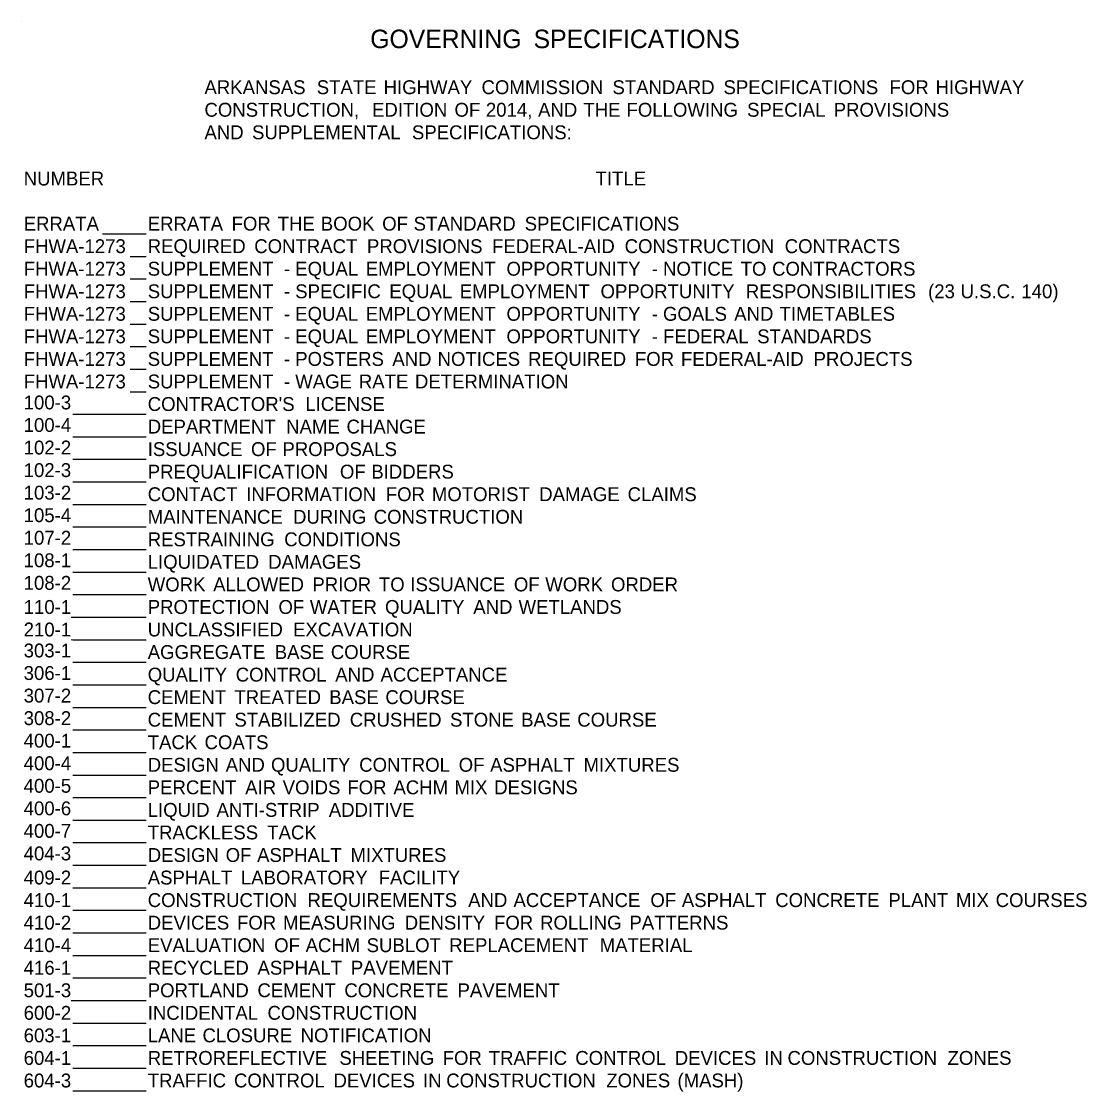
# Model space of a CAD drawing. Extents: x 2713 to 4149, y 471 to 1457.
# Drawn here: x 2713.2 to 3173.7, y 982.5 to 1445.3 of the extents above; entities that cross this region are included whole.
import ezdxf

# ---------------------------------------------------------------- set-up
doc = ezdxf.new("R2010")
doc.units = 0
doc.layers.add('Default', color=7, linetype='Continuous')
doc.layers.add('R_Border', color=7, linetype='Continuous')

msp = doc.modelspace()

# ---------------------------------------------------------------- linework, layer by layer
at = {"layer": 'R_Border'}
for p, q in [((2713.24, 1445.27), (2713.24, 1445.27)), ((2748.33, 1353.41), (2767.2, 1353.41)), ((2760.31, 1343.66), (2767.2, 1343.66)), ((2760.31, 1333.91), (2767.2, 1333.91)), ((2760.31, 1324.16), (2767.2, 1324.16)), ((2760.31, 1314.41), (2767.2, 1314.41)), ((2760.31, 1304.66), (2767.2, 1304.66)), ((2760.31, 1294.91), (2767.2, 1294.91)), ((2760.31, 1285.16), (2767.2, 1285.16)), ((2735.51, 1275.41), (2767.2, 1275.41)), ((2735.51, 1265.66), (2767.2, 1265.66)), ((2735.51, 1255.91), (2767.2, 1255.91)), ((2735.51, 1246.16), (2767.2, 1246.16)), ((2735.51, 1236.41), (2767.2, 1236.41)), ((2735.51, 1226.66), (2767.2, 1226.66)), ((2735.51, 1216.91), (2767.2, 1216.91)), ((2735.51, 1207.16), (2767.2, 1207.16)), ((2735.51, 1197.41), (2767.2, 1197.41)), ((2735.51, 1187.66), (2767.2, 1187.66)), ((2735.51, 1177.91), (2767.2, 1177.91)), ((2735.51, 1168.16), (2767.2, 1168.16)), ((2735.51, 1158.41), (2767.2, 1158.41)), ((2735.51, 1148.66), (2767.2, 1148.66)), ((2735.51, 1138.91), (2767.2, 1138.91)), ((2735.51, 1129.16), (2767.2, 1129.16)), ((2735.51, 1119.41), (2767.2, 1119.41)), ((2735.51, 1109.66), (2767.2, 1109.66)), ((2735.51, 1099.91), (2767.2, 1099.91)), ((2735.51, 1090.16), (2767.2, 1090.16)), ((2735.51, 1080.41), (2767.2, 1080.41)), ((2735.51, 1070.66), (2767.2, 1070.66)), ((2735.51, 1060.91), (2767.2, 1060.91)), ((2735.51, 1051.16), (2767.2, 1051.16)), ((2735.51, 1041.41), (2767.2, 1041.41)), ((2735.51, 1031.66), (2767.2, 1031.66)), ((2735.51, 1021.91), (2767.2, 1021.91)), ((2735.51, 1012.16), (2767.2, 1012.16)), ((2735.51, 1002.41), (2767.2, 1002.41)), ((2735.51, 992.66), (2767.2, 992.66)), ((2735.51, 982.91), (2767.2, 982.91))]:
    msp.add_line(p, q, dxfattribs=at)

# ---------------------------------------------------------------- texts
at = {"layer": 'Default'}
for s, height, p in [('GOVERNING', 8, (2864.03, 1433.71)), (' SPECIFICATIONS', 8, (2931.67, 1433.71)), ('           ARKANSAS', 6, (2767.84, 1413.81)), (' STATE', 6, (2838.67, 1413.81)), (' HIGHWAY', 6, (2867.58, 1413.81)), (' COMMISSION', 6, (2909.9, 1413.81)), (' STANDARD', 6, (2966.5, 1413.81)), (' SPECIFICATIONS', 6, (3014.5, 1413.81)), (' FOR', 6, (3086.27, 1413.81)), (' HIGHWAY', 6, (3106.18, 1413.81)), ('           CONSTRUCTION,', 6, (2767.84, 1404.06)), (' EDITION', 6, (2862.56, 1404.06)), (' OF', 6, (2898.21, 1404.06)), (' 2014,', 6, (2911.79, 1404.06)), (' AND', 6, (2934.34, 1404.06)), (' THE', 6, (2953.93, 1404.06)), (' FOLLOWING', 6, (2972.58, 1404.06)), (' SPECIAL', 6, (3024.68, 1404.06)), (' PROVISIONS', 6, (3062.12, 1404.06)), ('           AND', 6, (2767.84, 1394.31)), (' SUPPLEMENTAL', 6, (2810.7, 1394.31)), (' SPECIFICATIONS:', 6, (2879.82, 1394.31)), ('NUMBER', 6, (2714.22, 1374.32)), ('TITLE', 6, (2961.4, 1374.32)), ('ERRATA', 6, (2714.22, 1354.82)), ('ERRATA', 6, (2767.84, 1354.82)), (' FOR', 6, (2801.86, 1354.82)), (' THE', 6, (2821.78, 1354.82)), (' BOOK', 6, (2840.43, 1354.82)), (' OF', 6, (2866.96, 1354.82)), (' STANDARD', 6, (2880.55, 1354.82)), (' SPECIFICATIONS', 6, (2928.55, 1354.82)), ('FHWA-1273', 6, (2714.22, 1345.07)), ('REQUIRED', 6, (2767.84, 1345.07)), (' CONTRACT', 6, (2811.65, 1345.07)), (' PROVISIONS', 6, (2860.38, 1345.07)), (' FEDERAL-AID', 6, (2914.45, 1345.07)), (' CONSTRUCTION', 6, (2971.77, 1345.07)), (' CONTRACTS', 6, (3040.95, 1345.07)), ('FHWA-1273', 6, (2714.22, 1335.32)), ('SUPPLEMENT', 6, (2767.84, 1335.32)), (' -', 6, (2824.51, 1335.32)), (' EQUAL', 6, (2829.37, 1335.32)), (' EMPLOYMENT', 6, (2859.82, 1335.32)), (' OPPORTUNITY', 6, (2920.68, 1335.32)), (' -', 6, (2983.5, 1335.32)), (' NOTICE', 6, (2988.35, 1335.32)), (' TO', 6, (3021.91, 1335.32)), (' CONTRACTORS', 6, (3035.5, 1335.32)), ('FHWA-1273', 6, (2714.22, 1325.57)), ('SUPPLEMENT', 6, (2767.84, 1325.57)), (' -', 6, (2824.51, 1325.57)), (' SPECIFIC', 6, (2829.37, 1325.57)), (' EQUAL', 6, (2870.03, 1325.57)), (' EMPLOYMENT', 6, (2900.48, 1325.57)), (' OPPORTUNITY', 6, (2961.34, 1325.57)), (' RESPONSIBILITIES', 6, (3024.16, 1325.57)), (' (23', 6, (3102.92, 1325.57)), (' U.S.C.', 6, (3116.98, 1325.57)), (' 140)', 6, (3143.26, 1325.57)), ('FHWA-1273', 6, (2714.22, 1315.82)), ('SUPPLEMENT', 6, (2767.84, 1315.82)), (' EQUAL', 6, (2829.37, 1315.82)), (' EMPLOYMENT', 6, (2859.82, 1315.82)), (' OPPORTUNITY', 6, (2920.68, 1315.82)), (' GOALS', 6, (2988.35, 1315.82)), (' AND', 6, (3019.13, 1315.82)), (' TIMETABLES', 6, (3038.71, 1315.82)), (' -', 6, (2824.51, 1315.82)), (' -', 6, (2983.5, 1315.82)), ('FHWA-1273', 6, (2714.22, 1306.07)), ('SUPPLEMENT', 6, (2767.84, 1306.07)), (' EQUAL', 6, (2829.37, 1306.07)), (' EMPLOYMENT', 6, (2859.82, 1306.07)), (' OPPORTUNITY', 6, (2920.68, 1306.07)), (' FEDERAL', 6, (2988.35, 1306.07)), (' STANDARDS', 6, (3029.06, 1306.07)), (' -', 6, (2824.51, 1306.07)), (' -', 6, (2983.5, 1306.07)), ('FHWA-1273', 6, (2714.22, 1296.32)), ('SUPPLEMENT', 6, (2767.84, 1296.32)), (' POSTERS', 6, (2829.37, 1296.32)), (' AND', 6, (2871.33, 1296.32)), (' NOTICES', 6, (2890.91, 1296.32)), (' REQUIRED', 6, (2930.06, 1296.32)), (' FOR', 6, (2976.2, 1296.32)), (' FEDERAL-AID', 6, (2996.11, 1296.32)), (' PROJECTS', 6, (3053.43, 1296.32)), (' -', 6, (2824.51, 1296.32)), ('FHWA-1273', 6, (2714.22, 1286.57)), ('SUPPLEMENT', 6, (2767.84, 1286.57)), (' WAGE', 6, (2829.37, 1286.57)), (' RATE', 6, (2856.87, 1286.57)), (' DETERMINATION', 6, (2881.11, 1286.57)), (' -', 6, (2824.51, 1286.57)), ('100-3', 6, (2714.22, 1277.5)), ("CONTRACTOR'S", 6, (2767.84, 1276.82)), (' LICENSE', 6, (2833.75, 1276.82)), ('100-4', 6, (2714.22, 1267.75)), ('DEPARTMENT', 6, (2767.84, 1267.07)), (' NAME', 6, (2825.43, 1267.07)), (' CHANGE', 6, (2851.54, 1267.07)), ('102-2', 6, (2714.22, 1258)), ('ISSUANCE', 6, (2767.84, 1257.32)), (' OF', 6, (2810.26, 1257.32)), (' PROPOSALS', 6, (2823.84, 1257.32)), ('102-3', 6, (2714.22, 1248.25)), ('PREQUALIFICATION', 6, (2767.84, 1247.57)), (' OF', 6, (2848.68, 1247.57)), (' BIDDERS', 6, (2862.26, 1247.57)), ('103-2', 6, (2714.22, 1238.5)), ('CONTACT', 6, (2767.84, 1237.82)), (' INFORMATION', 6, (2808.19, 1237.82)), (' FOR', 6, (2868.52, 1237.82)), (' MOTORIST', 6, (2888.43, 1237.82)), (' DAMAGE', 6, (2934.83, 1237.82)), (' CLAIMS', 6, (2973.05, 1237.82)), ('105-4', 6, (2714.22, 1228.75)), ('MAINTENANCE', 6, (2767.84, 1228.07)), (' DURING', 6, (2828.42, 1228.07)), (' CONSTRUCTION', 6, (2863.29, 1228.07)), ('107-2', 6, (2714.22, 1219)), ('RESTRAINING', 6, (2767.84, 1218.32)), (' CONDITIONS', 6, (2824.61, 1218.32)), ('108-1', 6, (2714.22, 1209.25)), ('LIQUIDATED', 6, (2767.84, 1208.57)), (' DAMAGES', 6, (2817.7, 1208.57)), ('108-2', 6, (2714.22, 1199.5)), ('WORK', 6, (2767.84, 1198.82)), (' ALLOWED', 6, (2793.9, 1198.82)), (' PRIOR', 6, (2836.78, 1198.82)), (' TO', 6, (2865.54, 1198.82)), (' ISSUANCE', 6, (2879.14, 1198.82)), (' OF', 6, (2923.88, 1198.82)), (' WORK', 6, (2937.47, 1198.82)), (' ORDER', 6, (2965.86, 1198.82)), ('110-1______', 6, (2714.22, 1189.07)), ('PROTECTION', 6, (2767.84, 1189.07)), (' OF', 6, (2822.12, 1189.07)), (' WATER', 6, (2835.71, 1189.07)), (' QUALITY', 6, (2868.19, 1189.07)), (' AND', 6, (2906.33, 1189.07)), (' WETLANDS', 6, (2925.91, 1189.07)), ('210-1______', 6, (2714.22, 1179.32)), ('UNCLASSIFIED', 6, (2767.84, 1179.32)), (' EXCAVATION', 6, (2828.42, 1179.32)), ('303-1', 6, (2714.22, 1170.25)), ('AGGREGATE', 6, (2767.84, 1169.57)), (' BASE', 6, (2820.51, 1169.57)), (' COURSE', 6, (2844.76, 1169.57)), ('306-1', 6, (2714.22, 1160.5)), ('QUALITY', 6, (2767.84, 1159.82)), (' CONTROL', 6, (2803.65, 1159.82)), (' AND', 6, (2846.67, 1159.82)), (' ACCEPTANCE', 6, (2866.25, 1159.82)), ('307-2', 6, (2714.22, 1150.75)), ('CEMENT', 6, (2767.84, 1150.07)), (' TREATED', 6, (2803.07, 1150.07)), (' BASE', 6, (2844.08, 1150.07)), (' COURSE', 6, (2868.34, 1150.07)), ('308-2', 6, (2714.22, 1141)), ('CEMENT', 6, (2767.84, 1140.32)), (' STABILIZED', 6, (2803.07, 1140.32)), (' CRUSHED', 6, (2852.94, 1140.32)), (' STONE', 6, (2896.28, 1140.32)), (' BASE', 6, (2927.04, 1140.32)), (' COURSE', 6, (2951.29, 1140.32)), ('400-1', 6, (2714.22, 1131.25)), ('TACK', 6, (2767.84, 1130.57)), (' COATS', 6, (2790.18, 1130.57)), ('400-4', 6, (2714.22, 1121.5)), ('DESIGN', 6, (2767.84, 1120.82)), (' AND', 6, (2799.3, 1120.82)), (' QUALITY', 6, (2818.88, 1120.82)), (' CONTROL', 6, (2857.02, 1120.82)), (' OF', 6, (2900.04, 1120.82)), (' ASPHALT', 6, (2913.62, 1120.82)), (' MIXTURES', 6, (2953.99, 1120.82)), ('400-5', 6, (2714.22, 1111.75)), ('PERCENT', 6, (2767.84, 1111.07)), (' AIR', 6, (2807.74, 1111.07)), (' VOIDS', 6, (2823.93, 1111.07)), (' FOR', 6, (2851.9, 1111.07)), (' ACHM', 6, (2871.82, 1111.07)), (' MIX', 6, (2898.2, 1111.07)), (' DESIGNS', 6, (2915.38, 1111.07)), ('400-6', 6, (2714.22, 1102)), ('LIQUID', 6, (2767.84, 1101.32)), (' ANTI-STRIP', 6, (2795.34, 1101.32)), (' ADDITIVE', 6, (2843.88, 1101.32)), ('400-7', 6, (2714.22, 1092.25)), ('TRACKLESS', 6, (2767.84, 1091.57)), (' TACK', 6, (2817.26, 1091.57)), ('404-3', 6, (2714.22, 1082.5)), ('DESIGN', 6, (2767.84, 1081.82)), (' OF', 6, (2799.3, 1081.82)), (' ASPHALT', 6, (2812.89, 1081.82)), (' MIXTURES', 6, (2853.25, 1081.82)), ('409-2', 6, (2714.22, 1072.07)), ('ASPHALT', 6, (2767.84, 1072.07)), (' LABORATORY', 6, (2805.88, 1072.07)), (' FACILITY', 6, (2865.45, 1072.07)), ('410-1', 6, (2714.22, 1062.32)), ('CONSTRUCTION', 6, (2767.84, 1062.32)), (' REQUIREMENTS', 6, (2834.69, 1062.32)), (' AND', 6, (2904.13, 1062.32)), (' ACCEPTANCE', 6, (2923.71, 1062.32)), (' OF', 6, (2982.89, 1062.32)), (' ASPHALT', 6, (2996.48, 1062.32)), (' CONCRETE', 6, (3036.85, 1062.32)), (' PLANT', 6, (3085.78, 1062.32)), (' MIX', 6, (3114.96, 1062.32)), (' COURSES', 6, (3132.13, 1062.32)), ('410-2', 6, (2714.22, 1052.57)), ('DEVICES', 6, (2767.84, 1052.57)), (' FOR', 6, (2804.21, 1052.57)), (' MEASURING', 6, (2824.12, 1052.57)), (' DENSITY', 6, (2876.7, 1052.57)), (' FOR', 6, (2915.3, 1052.57)), (' ROLLING', 6, (2935.21, 1052.57)), (' PATTERNS', 6, (2973.82, 1052.57)), ('410-4', 6, (2714.22, 1042.82)), ('EVALUATION', 6, (2767.84, 1042.82)), (' OF', 6, (2820.27, 1042.82)), (' ACHM', 6, (2833.85, 1042.82)), (' SUBLOT', 6, (2860.24, 1042.82)), (' REPLACEMENT', 6, (2895.94, 1042.82)), (' MATERIAL', 6, (2960.99, 1042.82)), ('416-1', 6, (2714.22, 1033.07)), ('RECYCLED', 6, (2767.84, 1033.07)), (' ASPHALT', 6, (2813.05, 1033.07)), (' PAVEMENT', 6, (2853.42, 1033.07)), ('501-3______', 6, (2714.22, 1023.32)), ('PORTLAND', 6, (2767.84, 1023.32)), (' CEMENT', 6, (2813.05, 1023.32)), (' CONCRETE', 6, (2850.61, 1023.32)), (' PAVEMENT', 6, (2899.53, 1023.32)), ('600-2', 6, (2714.22, 1013.57)), ('INCIDENTAL', 6, (2767.84, 1013.57)), (' CONSTRUCTION', 6, (2817.39, 1013.57)), ('603-1', 6, (2714.22, 1003.82)), ('LANE', 6, (2767.84, 1003.82)), (' CLOSURE', 6, (2789.29, 1003.82)), (' NOTIFICATION', 6, (2831.7, 1003.82)), ('604-1', 6, (2714.22, 994.07)), ('RETROREFLECTIVE', 6, (2767.84, 994.07)), (' SHEETING', 6, (2848.45, 994.07)), (' FOR', 6, (2893.11, 994.07)), (' TRAFFIC', 6, (2913.02, 994.07)), (' CONTROL', 6, (2950.42, 994.07)), (' DEVICES', 6, (2993.43, 994.07)), (' IN', 6, (3032.13, 994.07)), (' CONSTRUCTION', 6, (3042.16, 994.07)), (' ZONES', 6, (3111.34, 994.07)), ('604-3', 6, (2714.22, 984.32)), ('TRAFFIC', 6, (2767.84, 984.32)), (' CONTROL', 6, (2802.9, 984.32)), (' DEVICES', 6, (2845.92, 984.32)), (' IN', 6, (2884.62, 984.32)), (' CONSTRUCTION', 6, (2894.65, 984.32)), (' ZONES', 6, (2963.82, 984.32)), (' (MASH)', 6, (2994.6, 984.32))]:
    msp.add_text(s, height=height, dxfattribs=at).set_placement(p)

doc.saveas('drawing.dxf')
